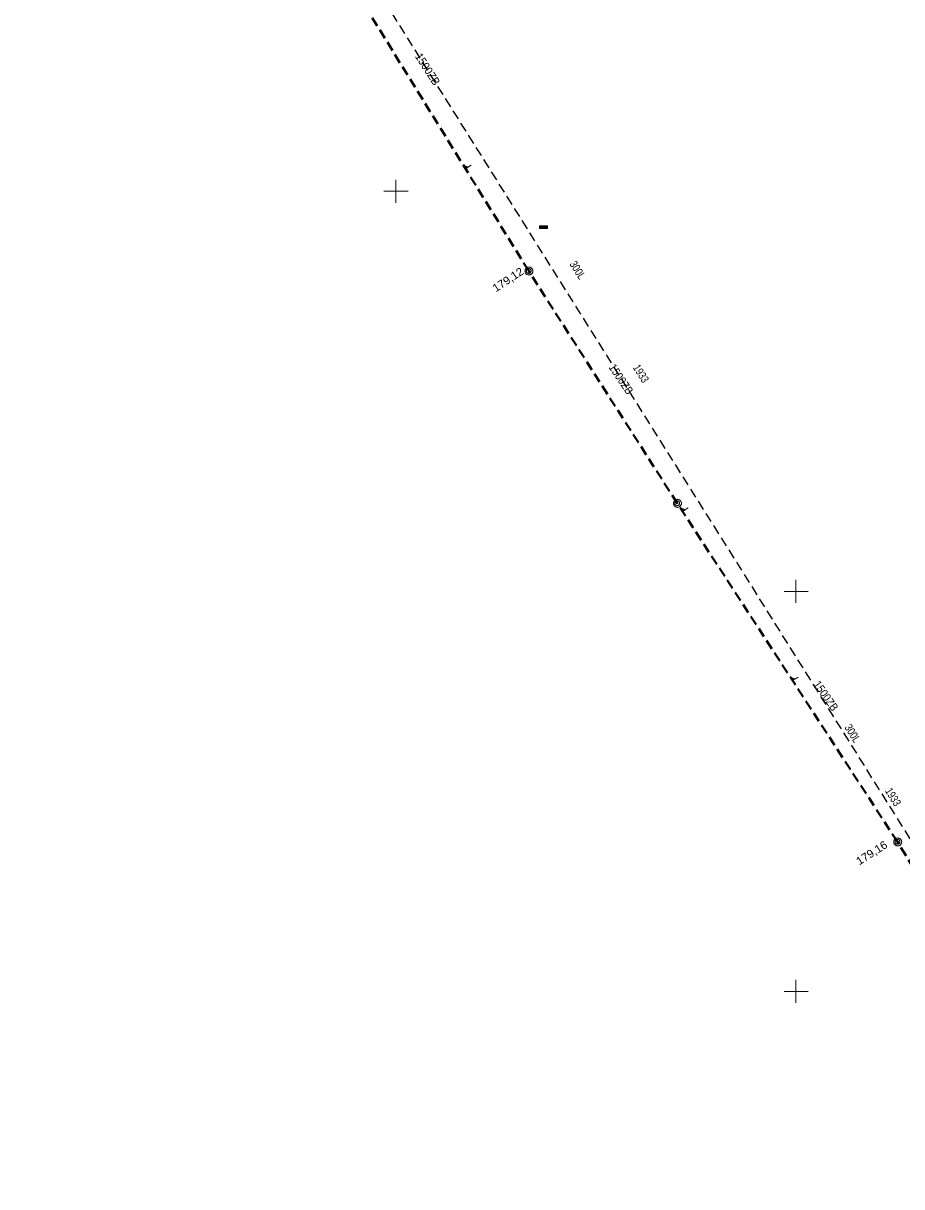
# Model space of a CAD drawing. Extents: x -740851 to -738888, y -1041382 to -1040235.
# Drawn here: x -739496.6 to -739386.8, y -1041074.4 to -1040929 of the extents above; entities that cross this region are included whole.
import ezdxf

# ---------------------------------------------------------------- set-up
doc = ezdxf.new("R2010")
doc.units = 0
doc.header["$LTSCALE"] = 0.4
doc.linetypes.add('MEDIUM_DASHED', pattern=[4.5, 3, -1.5])
for name, color, linetype, lineweight in [('1', 7, 'Continuous', 13), ('18', 7, 'Continuous', 13), ('8', 7, 'Continuous', 13)]:
    doc.layers.add(name, color=color, linetype=linetype, lineweight=lineweight)

msp = doc.modelspace()

# ---------------------------------------------------------------- hatches: boundary and pattern name
at = {"layer": '18'}
msp.add_hatch(color=256, dxfattribs=at).paths.add_polyline_path([(-739432.03, -1040954.33), (-739432.03, -1040954.67), (-739431.03, -1040954.67), (-739431.03, -1040954.33)])

# ---------------------------------------------------------------- linework, layer by layer
at = {"layer": '1'}
for p, q in [((-739450, -1040948.571), (-739450, -1040951.429)), ((-739451.48, -1040950), (-739448.48, -1040950)), ((-739400, -1040998.571), (-739400, -1041001.429)), ((-739400, -1040998.571), (-739400, -1041001.429)), ((-739401.48, -1041000), (-739398.48, -1041000)), ((-739401.48, -1041000), (-739398.48, -1041000)), ((-739400, -1041048.571), (-739400, -1041051.429)), ((-739401.48, -1041050), (-739398.48, -1041050))]:
    msp.add_line(p, q, dxfattribs=at)
at = {"layer": '18', "linetype": 'MEDIUM_DASHED', "lineweight": 40}
for p, q in [((-739433.4, -1040959.96), (-739462.93, -1040912.16)), ((-739414.84, -1040988.99), (-739433.4, -1040959.96)), ((-739387.32, -1041031.31), (-739414.84, -1040988.99)), ((-739360.74, -1041074.41), (-739387.32, -1041031.31))]:
    msp.add_line(p, q, dxfattribs=at)
at = {"layer": '18'}
msp.add_line((-739432.03, -1040954.33), (-739431.03, -1040954.67), dxfattribs=at)
for points in [[(-739440.597, -1040946.754), (-739441.291, -1040947.183), (-739441.597, -1040946.687), (-739440.978, -1040946.989)], [(-739441.07, -1040946.996), (-739441.272, -1040947.12), (-739441.468, -1040946.804), (-739441.068, -1040946.999)], [(-739441.166, -1040947.004), (-739441.267, -1040947.067), (-739441.367, -1040946.904), (-739441.164, -1040947.008)], [(-739413.491, -1040989.566), (-739414.174, -1040990.01), (-739414.491, -1040989.523), (-739413.866, -1040989.81)], [(-739413.958, -1040989.818), (-739414.157, -1040989.948), (-739414.359, -1040989.636), (-739413.956, -1040989.822)], [(-739414.053, -1040989.829), (-739414.153, -1040989.894), (-739414.256, -1040989.734), (-739414.051, -1040989.832)], [(-739399.737, -1041010.717), (-739400.42, -1041011.161), (-739400.737, -1041010.674), (-739400.112, -1041010.961)], [(-739400.204, -1041010.97), (-739400.403, -1041011.099), (-739400.605, -1041010.788), (-739400.202, -1041010.973)], [(-739400.299, -1041010.98), (-739400.398, -1041011.045), (-739400.502, -1041010.885), (-739400.297, -1041010.984)]]:
    msp.add_lwpolyline(points, dxfattribs=at)
for points in [[(-739432.03, -1040954.33), (-739432.03, -1040954.67), (-739431.03, -1040954.67), (-739431.03, -1040954.33)], [(-739432.87, -1040959.97), (-739432.88, -1040959.92), (-739432.88, -1040959.87), (-739432.9, -1040959.82), (-739432.92, -1040959.77), (-739432.94, -1040959.72), (-739432.97, -1040959.68), (-739433, -1040959.64), (-739433.04, -1040959.6), (-739433.08, -1040959.57), (-739433.12, -1040959.54), (-739433.17, -1040959.52), (-739433.22, -1040959.5), (-739433.27, -1040959.48), (-739433.32, -1040959.48), (-739433.37, -1040959.47), (-739433.42, -1040959.48), (-739433.47, -1040959.48), (-739433.52, -1040959.5), (-739433.57, -1040959.52), (-739433.62, -1040959.54), (-739433.66, -1040959.57), (-739433.7, -1040959.6), (-739433.74, -1040959.64), (-739433.77, -1040959.68), (-739433.8, -1040959.72), (-739433.82, -1040959.77), (-739433.84, -1040959.82), (-739433.86, -1040959.87), (-739433.86, -1040959.92), (-739433.87, -1040959.97), (-739433.86, -1040960.02), (-739433.86, -1040960.07), (-739433.84, -1040960.12), (-739433.82, -1040960.17), (-739433.8, -1040960.22), (-739433.77, -1040960.26), (-739433.74, -1040960.3), (-739433.7, -1040960.34), (-739433.66, -1040960.37), (-739433.62, -1040960.4), (-739433.57, -1040960.42), (-739433.52, -1040960.44), (-739433.47, -1040960.46), (-739433.42, -1040960.46), (-739433.37, -1040960.47), (-739433.32, -1040960.46), (-739433.27, -1040960.46), (-739433.22, -1040960.44), (-739433.17, -1040960.42), (-739433.12, -1040960.4), (-739433.08, -1040960.37), (-739433.04, -1040960.34), (-739433, -1040960.3), (-739432.97, -1040960.26), (-739432.94, -1040960.22), (-739432.92, -1040960.17), (-739432.9, -1040960.12), (-739432.88, -1040960.07), (-739432.88, -1040960.02)], [(-739433.1, -1040959.96), (-739433.1, -1040959.93), (-739433.106, -1040959.9), (-739433.112, -1040959.87), (-739433.124, -1040959.84), (-739433.142, -1040959.81), (-739433.16, -1040959.786), (-739433.178, -1040959.762), (-739433.202, -1040959.738), (-739433.226, -1040959.72), (-739433.25, -1040959.702), (-739433.28, -1040959.684), (-739433.31, -1040959.672), (-739433.34, -1040959.666), (-739433.37, -1040959.66), (-739433.4, -1040959.66), (-739433.43, -1040959.66), (-739433.46, -1040959.666), (-739433.49, -1040959.672), (-739433.52, -1040959.684), (-739433.55, -1040959.702), (-739433.574, -1040959.72), (-739433.598, -1040959.738), (-739433.622, -1040959.762), (-739433.64, -1040959.786), (-739433.658, -1040959.81), (-739433.676, -1040959.84), (-739433.688, -1040959.87), (-739433.694, -1040959.9), (-739433.7, -1040959.93), (-739433.7, -1040959.96), (-739433.7, -1040959.99), (-739433.694, -1040960.02), (-739433.688, -1040960.05), (-739433.676, -1040960.08), (-739433.658, -1040960.11), (-739433.64, -1040960.134), (-739433.622, -1040960.158), (-739433.598, -1040960.182), (-739433.574, -1040960.2), (-739433.55, -1040960.218), (-739433.52, -1040960.236), (-739433.49, -1040960.248), (-739433.46, -1040960.254), (-739433.43, -1040960.26), (-739433.4, -1040960.26), (-739433.37, -1040960.26), (-739433.34, -1040960.254), (-739433.31, -1040960.248), (-739433.28, -1040960.236), (-739433.25, -1040960.218), (-739433.226, -1040960.2), (-739433.202, -1040960.182), (-739433.178, -1040960.158), (-739433.16, -1040960.134), (-739433.142, -1040960.11), (-739433.124, -1040960.08), (-739433.112, -1040960.05), (-739433.106, -1040960.02), (-739433.1, -1040959.99)], [(-739414.31, -1040989), (-739414.32, -1040988.95), (-739414.32, -1040988.9), (-739414.34, -1040988.85), (-739414.36, -1040988.8), (-739414.38, -1040988.75), (-739414.41, -1040988.71), (-739414.44, -1040988.67), (-739414.48, -1040988.63), (-739414.52, -1040988.6), (-739414.56, -1040988.57), (-739414.61, -1040988.55), (-739414.66, -1040988.53), (-739414.71, -1040988.51), (-739414.76, -1040988.51), (-739414.81, -1040988.5), (-739414.86, -1040988.51), (-739414.91, -1040988.51), (-739414.96, -1040988.53), (-739415.01, -1040988.55), (-739415.06, -1040988.57), (-739415.1, -1040988.6), (-739415.14, -1040988.63), (-739415.18, -1040988.67), (-739415.21, -1040988.71), (-739415.24, -1040988.75), (-739415.26, -1040988.8), (-739415.28, -1040988.85), (-739415.3, -1040988.9), (-739415.3, -1040988.95), (-739415.31, -1040989), (-739415.3, -1040989.05), (-739415.3, -1040989.1), (-739415.28, -1040989.15), (-739415.26, -1040989.2), (-739415.24, -1040989.25), (-739415.21, -1040989.29), (-739415.18, -1040989.33), (-739415.14, -1040989.37), (-739415.1, -1040989.4), (-739415.06, -1040989.43), (-739415.01, -1040989.45), (-739414.96, -1040989.47), (-739414.91, -1040989.49), (-739414.86, -1040989.49), (-739414.81, -1040989.5), (-739414.76, -1040989.49), (-739414.71, -1040989.49), (-739414.66, -1040989.47), (-739414.61, -1040989.45), (-739414.56, -1040989.43), (-739414.52, -1040989.4), (-739414.48, -1040989.37), (-739414.44, -1040989.33), (-739414.41, -1040989.29), (-739414.38, -1040989.25), (-739414.36, -1040989.2), (-739414.34, -1040989.15), (-739414.32, -1040989.1), (-739414.32, -1040989.05)], [(-739414.54, -1040988.99), (-739414.54, -1040988.96), (-739414.546, -1040988.93), (-739414.552, -1040988.9), (-739414.564, -1040988.87), (-739414.582, -1040988.84), (-739414.6, -1040988.816), (-739414.618, -1040988.792), (-739414.642, -1040988.768), (-739414.666, -1040988.75), (-739414.69, -1040988.732), (-739414.72, -1040988.714), (-739414.75, -1040988.702), (-739414.78, -1040988.696), (-739414.81, -1040988.69), (-739414.84, -1040988.69), (-739414.87, -1040988.69), (-739414.9, -1040988.696), (-739414.93, -1040988.702), (-739414.96, -1040988.714), (-739414.99, -1040988.732), (-739415.014, -1040988.75), (-739415.038, -1040988.768), (-739415.062, -1040988.792), (-739415.08, -1040988.816), (-739415.098, -1040988.84), (-739415.116, -1040988.87), (-739415.128, -1040988.9), (-739415.134, -1040988.93), (-739415.14, -1040988.96), (-739415.14, -1040988.99), (-739415.14, -1040989.02), (-739415.134, -1040989.05), (-739415.128, -1040989.08), (-739415.116, -1040989.11), (-739415.098, -1040989.14), (-739415.08, -1040989.164), (-739415.062, -1040989.188), (-739415.038, -1040989.212), (-739415.014, -1040989.23), (-739414.99, -1040989.248), (-739414.96, -1040989.266), (-739414.93, -1040989.278), (-739414.9, -1040989.284), (-739414.87, -1040989.29), (-739414.84, -1040989.29), (-739414.81, -1040989.29), (-739414.78, -1040989.284), (-739414.75, -1040989.278), (-739414.72, -1040989.266), (-739414.69, -1040989.248), (-739414.666, -1040989.23), (-739414.642, -1040989.212), (-739414.618, -1040989.188), (-739414.6, -1040989.164), (-739414.582, -1040989.14), (-739414.564, -1040989.11), (-739414.552, -1040989.08), (-739414.546, -1040989.05), (-739414.54, -1040989.02)], [(-739386.79, -1041031.32), (-739386.8, -1041031.27), (-739386.8, -1041031.22), (-739386.82, -1041031.17), (-739386.84, -1041031.12), (-739386.86, -1041031.07), (-739386.89, -1041031.03), (-739386.92, -1041030.99), (-739386.96, -1041030.95), (-739387, -1041030.92), (-739387.04, -1041030.89), (-739387.09, -1041030.87), (-739387.14, -1041030.85), (-739387.19, -1041030.83), (-739387.24, -1041030.83), (-739387.29, -1041030.82), (-739387.34, -1041030.83), (-739387.39, -1041030.83), (-739387.44, -1041030.85), (-739387.49, -1041030.87), (-739387.54, -1041030.89), (-739387.58, -1041030.92), (-739387.62, -1041030.95), (-739387.66, -1041030.99), (-739387.69, -1041031.03), (-739387.72, -1041031.07), (-739387.74, -1041031.12), (-739387.76, -1041031.17), (-739387.78, -1041031.22), (-739387.78, -1041031.27), (-739387.79, -1041031.32), (-739387.78, -1041031.37), (-739387.78, -1041031.42), (-739387.76, -1041031.47), (-739387.74, -1041031.52), (-739387.72, -1041031.57), (-739387.69, -1041031.61), (-739387.66, -1041031.65), (-739387.62, -1041031.69), (-739387.58, -1041031.72), (-739387.54, -1041031.75), (-739387.49, -1041031.77), (-739387.44, -1041031.79), (-739387.39, -1041031.81), (-739387.34, -1041031.81), (-739387.29, -1041031.82), (-739387.24, -1041031.81), (-739387.19, -1041031.81), (-739387.14, -1041031.79), (-739387.09, -1041031.77), (-739387.04, -1041031.75), (-739387, -1041031.72), (-739386.96, -1041031.69), (-739386.92, -1041031.65), (-739386.89, -1041031.61), (-739386.86, -1041031.57), (-739386.84, -1041031.52), (-739386.82, -1041031.47), (-739386.8, -1041031.42), (-739386.8, -1041031.37)], [(-739387.02, -1041031.31), (-739387.02, -1041031.28), (-739387.026, -1041031.25), (-739387.032, -1041031.22), (-739387.044, -1041031.19), (-739387.062, -1041031.16), (-739387.08, -1041031.136), (-739387.098, -1041031.112), (-739387.122, -1041031.088), (-739387.146, -1041031.07), (-739387.17, -1041031.052), (-739387.2, -1041031.034), (-739387.23, -1041031.022), (-739387.26, -1041031.016), (-739387.29, -1041031.01), (-739387.32, -1041031.01), (-739387.35, -1041031.01), (-739387.38, -1041031.016), (-739387.41, -1041031.022), (-739387.44, -1041031.034), (-739387.47, -1041031.052), (-739387.494, -1041031.07), (-739387.518, -1041031.088), (-739387.542, -1041031.112), (-739387.56, -1041031.136), (-739387.578, -1041031.16), (-739387.596, -1041031.19), (-739387.608, -1041031.22), (-739387.614, -1041031.25), (-739387.62, -1041031.28), (-739387.62, -1041031.31), (-739387.62, -1041031.34), (-739387.614, -1041031.37), (-739387.608, -1041031.4), (-739387.596, -1041031.43), (-739387.578, -1041031.46), (-739387.56, -1041031.484), (-739387.542, -1041031.508), (-739387.518, -1041031.532), (-739387.494, -1041031.55), (-739387.47, -1041031.568), (-739387.44, -1041031.586), (-739387.41, -1041031.598), (-739387.38, -1041031.604), (-739387.35, -1041031.61), (-739387.32, -1041031.61), (-739387.29, -1041031.61), (-739387.26, -1041031.604), (-739387.23, -1041031.598), (-739387.2, -1041031.586), (-739387.17, -1041031.568), (-739387.146, -1041031.55), (-739387.122, -1041031.532), (-739387.098, -1041031.508), (-739387.08, -1041031.484), (-739387.062, -1041031.46), (-739387.044, -1041031.43), (-739387.032, -1041031.4), (-739387.026, -1041031.37), (-739387.02, -1041031.34)]]:
    msp.add_lwpolyline(points, close=True, dxfattribs=at)
at = {"layer": '8', "linetype": 'MEDIUM_DASHED', "lineweight": 25}
msp.add_lwpolyline([(-739496.554, -1040855.122), (-739491.67, -1040862.2), (-739374.679, -1041048.562)], dxfattribs=at)

# ---------------------------------------------------------------- texts
at = {"layer": '18'}
for s, rotation, width, p in [('1500ZB', 302.707, 0.95, (-739447.655, -1040933.13)), ('179,12', 33.495, 1.05, (-739437.504, -1040962.643)), ('1500ZB', 303.914, 0.9, (-739423.445, -1040972.001)), ('1500ZB', 304.875, 0.9, (-739397.874, -1041011.622)), ('179,16', 32.636, 1.05, (-739392.081, -1041034.259))]:
    msp.add_text(s, height=1, rotation=rotation, dxfattribs=dict(at, width=width)).set_placement(p)
at = {"layer": '8', "width": 0.8}
for s, p in [('300L', (-739428.336, -1040959.093)), ('1933', (-739420.414, -1040972.036)), ('300L', (-739393.98, -1041017.009)), ('1933', (-739388.916, -1041024.948))]:
    msp.add_text(s, height=1, rotation=302.119, dxfattribs=at).set_placement(p)

doc.saveas('drawing.dxf')
